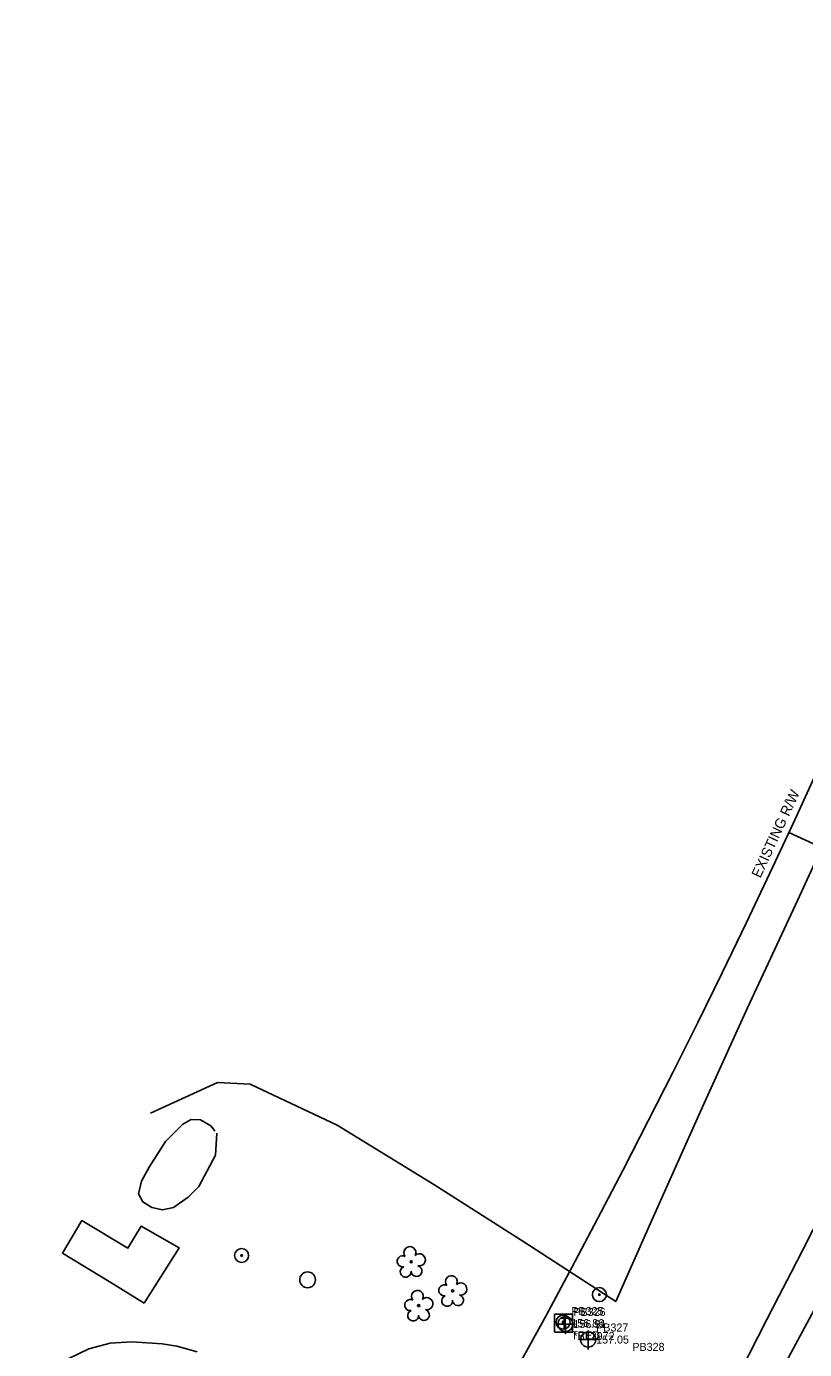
# Model space of a CAD drawing. Extents: x 2262665 to 2270527, y 505476 to 514960.
# Drawn here: x 2265696.4 to 2265938.9, y 509036.7 to 509448.8 of the extents above; entities that cross this region are included whole.
import ezdxf

# ---------------------------------------------------------------- set-up
doc = ezdxf.new("R2010")
doc.units = 0
for name, color, linetype in [('Exist Building Foundations', 7, 'Continuous'), ('Exist Horizontal Alignment', 7, 'Continuous'), ('Exist Other Culture Fence Line', 7, 'Continuous'), ('Exist Other Culture Located Object CELL', 7, 'Continuous'), ('Exist Right of Way Control of Access Line', 7, 'Continuous'), ('Exist Right of Way Line Text', 7, 'Continuous'), ('Exist Right of Way Width CELL', 7, 'Continuous'), ('Exist Roads EOP', 7, 'Continuous'), ('Exist Roads EOP Other', 7, 'Continuous'), ('Exist Roads EOT', 7, 'Continuous'), ('Exist Utilities Other Pole CELL', 7, 'Continuous'), ('Exist Utilities Telephone Pedestal CELL', 7, 'Continuous'), ('Exist Utilities Telephone Pedestal Cogo Comment', 7, 'Continuous'), ('Exist Utilities Telephone Pedestal Cogo Elevation', 7, 'Continuous'), ('Exist Utilities Telephone Pedestal Cogo Number', 7, 'Continuous'), ('Exist Utilities Telephone UG Conduit SUE LOS B Cogo Comment', 7, 'Continuous'), ('Exist Utilities Telephone UG Conduit SUE LOS B Cogo Elevation', 7, 'Continuous'), ('Exist Utilities Telephone UG Conduit SUE LOS B Cogo Number', 7, 'Continuous'), ('Exist Utilities Telephone UG Conduit SUE LOS B Cogo Point CELL', 7, 'Continuous'), ('Exist Vegetation Tree CELL', 7, 'Continuous'), ('Exist Vegetation Woods Line', 7, 'Continuous')]:
    doc.layers.add(name, color=color, linetype=linetype)

msp = doc.modelspace()

# ---------------------------------------------------------------- linework, layer by layer
at = {"layer": 'Exist Building Foundations'}
msp.add_lwpolyline([(2265733.1, 509051.13), (2265743.96, 509068.42), (2265732.17, 509075.14), (2265727.99, 509068.3), (2265713.69, 509076.88), (2265707.6, 509066.71), (2265722.21, 509057.87)], close=True, dxfattribs=at)
at = {"layer": 'Exist Horizontal Alignment'}
msp.add_arc((2263436.25, 510359.19), 2882, 309.60499, 355.6461, dxfattribs=at)
at = {"layer": 'Exist Other Culture Fence Line'}
for points in [[(2265935.11, 509632.71), (2265963.38, 509609.48), (2265980.51, 509595.58), (2265997.14, 509582.86), (2266019.57, 509564.09), (2266044.87, 509543.13), (2266056.13, 509534.43), (2266088.53, 509508.87), (2266073.89, 509477.67), (2266057.87, 509441.48), (2266042.86, 509409.08), (2266015.5, 509349.02), (2265987.41, 509287.57), (2265963.64, 509234.96), (2265936.09, 509175.26), (2265921.16, 509143.13)], [(2265921.16, 509143.13), (2265907.17, 509112.52), (2265891.27, 509076.97), (2265880.04, 509051.63), (2265851.38, 509070.27), (2265823.34, 509088.08), (2265793.2, 509106.61), (2265766.15, 509119.39), (2265755.93, 509119.91), (2265749.62, 509116.96), (2265735.07, 509110.35)]]:
    msp.add_lwpolyline(points, dxfattribs=at)
at = {"layer": 'Exist Other Culture Located Object CELL'}
for centre, radius in [((2265763.45, 509066), 2.18), ((2265763.45, 509066), 0.24), ((2265874.95, 509053.81), 2.18), ((2265874.95, 509053.81), 0.24), ((2265863.65, 509045.26), 2.18), ((2265863.65, 509045.26), 0.24)]:
    msp.add_circle(centre, radius, dxfattribs=at)
at = {"layer": 'Exist Right of Way Control of Access Line'}
for radius, end in [(2754.56, 355.6461), (2954.56, 339.73535)]:
    msp.add_arc((2263436.25, 510359.19), radius, 309.60499, end, dxfattribs=at)
at = {"layer": 'Exist Right of Way Width CELL'}
msp.add_line((2265934, 509197.8), (2265976.35, 509178.11), dxfattribs=at)
at = {"layer": 'Exist Roads EOP'}
for points in [[(2265927.16, 509046.11), (2265930.9, 509053.32), (2265934.65, 509060.53), (2265938.39, 509067.73), (2265941.51, 509073.88), (2265944.62, 509080.03), (2265947.73, 509086.17), (2265951.43, 509093.46), (2265955.61, 509101.23)], [(2265884.33, 508968.55), (2265888.98, 508976.67), (2265893.63, 508984.79), (2265898.28, 508992.91), (2265902.94, 509001.03), (2265907.58, 509009.55), (2265912.22, 509018.06), (2265916.86, 509026.58), (2265921.5, 509035.1), (2265927.16, 509046.11)]]:
    msp.add_lwpolyline(points, dxfattribs=at)
at = {"layer": 'Exist Roads EOP Other'}
msp.add_lwpolyline([(2265749.56, 509035.97), (2265743.28, 509037.71), (2265738.66, 509038.52), (2265729.2, 509039.08), (2265722.49, 509038.65), (2265715.82, 509036.94), (2265709.35, 509033.85)], dxfattribs=at)
at = {"layer": 'Exist Roads EOT'}
msp.add_lwpolyline([(2265966, 509095.96), (2265942.58, 509050.45), (2265904.19, 508979.11), (2265863.41, 508909.33), (2265820.21, 508839.95), (2265775.13, 508772.3)], dxfattribs=at)
at = {"layer": 'Exist Utilities Other Pole CELL'}
msp.add_circle((2265784.01, 509058.41), 2.46, dxfattribs=at)
at = {"layer": 'Exist Utilities Telephone Pedestal CELL'}
msp.add_line((2265863.71, 509044.92), (2265863.71, 509044.92), dxfattribs=at)
msp.add_lwpolyline([(2265860.98, 509042.09), (2265866.58, 509042.09), (2265866.58, 509047.69), (2265860.98, 509047.69), (2265860.98, 509042.09)], dxfattribs=at)
at = {"layer": 'Exist Utilities Telephone UG Conduit SUE LOS B Cogo Point CELL'}
for points in [[(2265864.33, 509047.46), (2265864.37, 509041.65), (2265864.35, 509044.65), (2265867.37, 509044.65), (2265861.37, 509044.65)], [(2265871.43, 509042.64), (2265871.46, 509036.82), (2265871.44, 509039.82), (2265874.46, 509039.82), (2265868.46, 509039.82)]]:
    msp.add_lwpolyline(points, dxfattribs=at)
for centre in [(2265864.37, 509044.65), (2265871.46, 509039.82)]:
    msp.add_circle(centre, 2.34, dxfattribs=at)
at = {"layer": 'Exist Vegetation Tree CELL'}
for p, q in [((2265816.29, 509064.05), (2265816.29, 509064.05)), ((2265829.22, 509054.98), (2265829.22, 509054.98)), ((2265818.62, 509050.39), (2265818.62, 509050.39))]:
    msp.add_line(p, q, dxfattribs=at)
for centre in [(2265816.29, 509064.05), (2265829.22, 509054.98), (2265818.62, 509050.39)]:
    msp.add_circle(centre, 0.326, dxfattribs=at)
for centre, radius, start, end in [((2265815.9, 509066.92), 1.86, 330.1651, 219.7134), ((2265813.68, 509064.2), 1.73, 62.6636, 279.3457), ((2265818.84, 509064.64), 1.9, 257.1011, 134.1999), ((2265814.58, 509060.93), 1.69, 111.5671, 6.231), ((2265817.96, 509061.15), 1.7, 181.2822, 74.56), ((2265826.61, 509055.14), 1.73, 62.6636, 279.3457), ((2265828.83, 509057.85), 1.86, 330.1651, 219.7134), ((2265831.76, 509055.57), 1.9, 257.1011, 134.1999), ((2265816.01, 509050.54), 1.73, 62.6636, 279.3457), ((2265818.24, 509053.26), 1.86, 330.1651, 219.7134), ((2265821.17, 509050.98), 1.9, 257.1011, 134.1999), ((2265827.51, 509051.86), 1.69, 111.5671, 6.231), ((2265830.89, 509052.08), 1.7, 181.2822, 74.56), ((2265816.92, 509047.27), 1.69, 111.5671, 6.231), ((2265820.29, 509047.49), 1.7, 181.2822, 74.56)]:
    msp.add_arc(centre, radius, start, end, dxfattribs=at)
at = {"layer": 'Exist Vegetation Woods Line'}
msp.add_lwpolyline([(2265755.69, 509104.13), (2265755.35, 509097.24), (2265750.1, 509087.54), (2265746.8, 509084.22), (2265742.22, 509080.96), (2265738.83, 509080.24), (2265735.45, 509080.99), (2265732.7, 509082.68), (2265731.35, 509085.17), (2265732.25, 509089.17), (2265734.68, 509093.5), (2265739.71, 509101.49), (2265745.12, 509106.91), (2265747.72, 509108.32), (2265750.62, 509108.3), (2265753.83, 509106.37), (2265754.66, 509105.37), (2265755.05, 509104.76)], dxfattribs=at)

# ---------------------------------------------------------------- texts
at = {"layer": 'Exist Right of Way Line Text'}
msp.add_text('EXISTING R/W', height=3.2, rotation=65.1621, dxfattribs=at).set_placement((2265925.11, 509183.36))
at = {"layer": 'Exist Utilities Telephone Pedestal CELL'}
msp.add_text('T', height=3.42, dxfattribs=at).set_placement((2265862.58, 509043.2))
at = {"layer": 'Exist Utilities Telephone Pedestal Cogo Comment'}
msp.add_text('TPED', height=2.5, dxfattribs=at).set_placement((2265866.21, 509039.92))
at = {"layer": 'Exist Utilities Telephone Pedestal Cogo Elevation'}
msp.add_text('156.86', height=2.5, dxfattribs=at).set_placement((2265866.21, 509043.67))
at = {"layer": 'Exist Utilities Telephone Pedestal Cogo Number'}
msp.add_text('PB325', height=2.5, dxfattribs=at).set_placement((2265866.21, 509047.42))
at = {"layer": 'Exist Utilities Telephone UG Conduit SUE LOS B Cogo Comment'}
msp.add_text('*BL2972', height=2.5, dxfattribs=at).set_placement((2265866.85, 509039.65))
at = {"layer": 'Exist Utilities Telephone UG Conduit SUE LOS B Cogo Elevation'}
for s, p in [('156.91', (2265866.85, 509043.4)), ('157.05', (2265873.94, 509038.57))]:
    msp.add_text(s, height=2.5, dxfattribs=at).set_placement(p)
at = {"layer": 'Exist Utilities Telephone UG Conduit SUE LOS B Cogo Number'}
for s, p in [('PB326', (2265866.85, 509047.15)), ('PB327', (2265873.94, 509042.32)), ('PB328', (2265885.23, 509036.28))]:
    msp.add_text(s, height=2.5, dxfattribs=at).set_placement(p)

doc.saveas('drawing.dxf')
